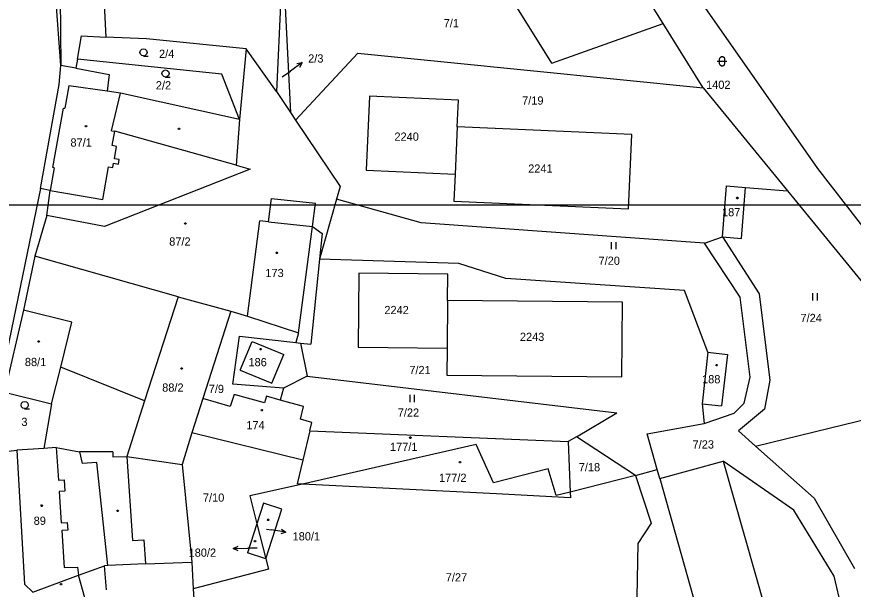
# Model space of a CAD drawing. Extents: x -802857 to -799647, y -1020285 to -1015884.
# Drawn here: x -801490 to -801316.9, y -1017579.5 to -1017461.1 of the extents above; entities that cross this region are included whole.
import ezdxf

# ---------------------------------------------------------------- set-up
doc = ezdxf.new("R2010")
doc.units = 0
for name, color, linetype in [('Default', 7, 'Continuous'), ('KLADY_ZMVM', 7, 'Continuous'), ('KN_HRANICE', 7, 'Continuous'), ('KN_KULTURY', 7, 'Continuous'), ('KN_PARCELY', 7, 'Continuous'), ('KN_SLUCKY', 7, 'Continuous')]:
    doc.layers.add(name, color=color, linetype=linetype)

# ---------------------------------------------------------------- blocks, each defined once
blk = doc.blocks.new('304')
at = {"layer": 'Default'}
blk.add_lwpolyline([(0, 0), (-0.38, 0.1), (-0.65, 0.37), (-0.75, 0.74), (-0.65, 1.11), (-0.38, 1.38), (-0.01, 1.48), (0.36, 1.38), (0.63, 1.11), (0.73, 0.73), (0.63, 0.35), (0.36, 0.08), (-0.02, -0.02), (0.98, -0.02)], dxfattribs=at)
blk = doc.blocks.new('306')
at = {"layer": 'Default'}
for p, q in [((-0.5, 1.5), (-0.5, 0)), ((0.5, 0), (0.5, 1.5))]:
    blk.add_line(p, q, dxfattribs=at)
blk = doc.blocks.new('316')
at = {"layer": 'Default'}
for points in [[(-0.5, 1.5), (-0.4, 1.79), (-0.15, 1.97), (0.16, 1.97), (0.41, 1.79), (0.51, 1.5), (0.51, 0.5), (0.41, 0.21), (0.16, 0.03), (-0.15, 0.03), (-0.4, 0.21), (-0.5, 0.5), (-0.5, 1.5)], [(-1, 1), (0.27, 1), (1, 1)]]:
    blk.add_lwpolyline(points, dxfattribs=at)
blk = doc.blocks.new('NAHRADNI_SYMBOL')
at = {"layer": 'Default'}
blk.add_lwpolyline([(0.09, 0.15), (0.18, 0), (0.09, -0.15), (-0.09, -0.15), (-0.18, 0), (-0.09, 0.15), (0.09, 0.15)], dxfattribs=at)
blk = doc.blocks.new('10292')
at = {"layer": 'Default'}
blk.add_line((0, 3), (0, 0), dxfattribs=at)
blk.add_lwpolyline([(-0.5, 2), (0, 3), (0.5, 2)], dxfattribs=at)
blk = doc.blocks.new('402')
at = {"layer": 'Default'}
blk.add_lwpolyline([(0.09, 0.15), (0.18, 0), (0.09, -0.15), (-0.09, -0.15), (-0.18, 0), (-0.09, 0.15), (0.09, 0.15)], dxfattribs=at)

msp = doc.modelspace()

# ---------------------------------------------------------------- linework, layer by layer
at = {"layer": 'KLADY_ZMVM'}
msp.add_lwpolyline([(-801875, -1017500), (-801250, -1017500), (-801043.11, -1017500)], dxfattribs=at)
at = {"layer": 'KN_HRANICE'}
for p, q in [((-801366.39, -1017432.38), (-801324.28, -1017492.5)), ((-801356.25, -1017462.47), (-801367.72, -1017444.15)), ((-801481.05, -1017452.5), (-801480.85, -1017471.15)), ((-801435.08, -1017451.54), (-801436.26, -1017476.56)), ((-801472.2, -1017452.64), (-801471.55, -1017465.31)), ((-801379.24, -1017470.71), (-801390.25, -1017453.11)), ((-801480.85, -1017471.15), (-801481.99, -1017455.66)), ((-801434.42, -1017459.09), (-801433.35, -1017480.9)), ((-801379.24, -1017470.71), (-801356.25, -1017462.47)), ((-801347.93, -1017475.78), (-801356.25, -1017462.47)), ((-801477.42, -1017469.86), (-801476.6, -1017465.01)), ((-801476.6, -1017465.01), (-801471.55, -1017465.31)), ((-801463.11, -1017465.64), (-801471.55, -1017465.31)), ((-801442.53, -1017467.71), (-801463.11, -1017465.64)), ((-801442.53, -1017467.71), (-801443.87, -1017482.3)), ((-801436.26, -1017476.56), (-801442.53, -1017467.71)), ((-801432.29, -1017482.48), (-801419.41, -1017468.61)), ((-801419.41, -1017468.61), (-801347.93, -1017475.78)), ((-801481.2, -1017475.07), (-801480.85, -1017471.15)), ((-801477.74, -1017471.72), (-801480.85, -1017471.15)), ((-801477.42, -1017469.86), (-801477.74, -1017471.72)), ((-801447.58, -1017472.97), (-801477.42, -1017469.86)), ((-801477.74, -1017471.72), (-801470.85, -1017473.01)), ((-801470.85, -1017473.01), (-801471.25, -1017476.47)), ((-801443.87, -1017482.3), (-801447.58, -1017472.97)), ((-801485.05, -1017496.6), (-801481.2, -1017475.07)), ((-801468.51, -1017476.86), (-801471.25, -1017476.47)), ((-801436.26, -1017476.56), (-801433.35, -1017480.9)), ((-801347.93, -1017475.78), (-801330.52, -1017497.1)), ((-801443.87, -1017482.3), (-801468.51, -1017476.86)), ((-801416.99, -1017477.52), (-801417.67, -1017492.81)), ((-801398.61, -1017478.34), (-801416.99, -1017477.52)), ((-801398.85, -1017483.83), (-801398.61, -1017478.34)), ((-801433.35, -1017480.9), (-801432.29, -1017482.48)), ((-801443.87, -1017482.3), (-801444.57, -1017491.8)), ((-801432.29, -1017482.48), (-801423.09, -1017496.22)), ((-801398.85, -1017483.83), (-801399.29, -1017493.63)), ((-801362.69, -1017485.45), (-801398.85, -1017483.83)), ((-801363.38, -1017500.83), (-801362.69, -1017485.45)), ((-801444.57, -1017491.8), (-801441.67, -1017492.59)), ((-801441.67, -1017492.59), (-801471.82, -1017504.46)), ((-801417.67, -1017492.81), (-801399.29, -1017493.63)), ((-801399.29, -1017493.63), (-801399.54, -1017499.22)), ((-801324.28, -1017492.5), (-801277.94, -1017552.4)), ((-801485.05, -1017496.6), (-801499.12, -1017563.93)), ((-801483.09, -1017497), (-801485.05, -1017496.6)), ((-801483.78, -1017502.18), (-801483.09, -1017497)), ((-801423.09, -1017496.22), (-801423.84, -1017498.84)), ((-801343.98, -1017506.62), (-801343.11, -1017496.06)), ((-801343.11, -1017496.06), (-801339.17, -1017496.38)), ((-801340.04, -1017506.94), (-801339.17, -1017496.38)), ((-801339.17, -1017496.38), (-801330.52, -1017497.1)), ((-801330.52, -1017497.1), (-801295.7, -1017539.76)), ((-801437.92, -1017503.51), (-801437.29, -1017498.66)), ((-801437.29, -1017498.66), (-801428.14, -1017499.64)), ((-801423.84, -1017498.84), (-801427.36, -1017511.23)), ((-801406.29, -1017503.73), (-801423.84, -1017498.84)), ((-801399.54, -1017499.22), (-801363.38, -1017500.83)), ((-801428.78, -1017504.49), (-801428.14, -1017499.64)), ((-801483.78, -1017502.18), (-801486.27, -1017510.58)), ((-801471.82, -1017504.46), (-801483.78, -1017502.18)), ((-801442.26, -1017523.04), (-801439.66, -1017503.32)), ((-801437.92, -1017503.51), (-801439.66, -1017503.32)), ((-801347.66, -1017507.88), (-801406.29, -1017503.73)), ((-801428.78, -1017504.49), (-801426.82, -1017505.92)), ((-801426.82, -1017505.92), (-801427.36, -1017511.23)), ((-801347.66, -1017507.88), (-801343.98, -1017506.62)), ((-801340.3, -1017519.09), (-801347.66, -1017507.88)), ((-801343.98, -1017506.62), (-801336.36, -1017518.38)), ((-801343.98, -1017506.62), (-801340.04, -1017506.94)), ((-801486.27, -1017510.58), (-801488.6, -1017521.78)), ((-801456.61, -1017519.04), (-801486.27, -1017510.58)), ((-801427.36, -1017511.23), (-801429.15, -1017528.81)), ((-801398.49, -1017512.08), (-801427.36, -1017511.23)), ((-801388.8, -1017515.22), (-801398.49, -1017512.08)), ((-801419.19, -1017514.13), (-801419.33, -1017529.43)), ((-801400.8, -1017514.3), (-801419.19, -1017514.13)), ((-801400.84, -1017519.79), (-801400.8, -1017514.3)), ((-801351.85, -1017517.73), (-801388.8, -1017515.22)), ((-801346.97, -1017530.44), (-801351.85, -1017517.73)), ((-801456.61, -1017519.04), (-801445.68, -1017521.95)), ((-801400.84, -1017519.79), (-801400.93, -1017529.6)), ((-801364.65, -1017520.13), (-801400.84, -1017519.79)), ((-801338.24, -1017535.6), (-801340.3, -1017519.09)), ((-801336.36, -1017518.38), (-801334.2, -1017536.23)), ((-801364.79, -1017535.52), (-801364.65, -1017520.13)), ((-801488.6, -1017521.78), (-801492.54, -1017538.69)), ((-801478.58, -1017524.23), (-801488.6, -1017521.78)), ((-801445.68, -1017521.95), (-801451.5, -1017540.03)), ((-801445.68, -1017521.95), (-801442.26, -1017523.04)), ((-801442.26, -1017523.04), (-801431.67, -1017526.43)), ((-801480.88, -1017533.53), (-801478.58, -1017524.23)), ((-801431.67, -1017526.43), (-801432.23, -1017528.46)), ((-801445.24, -1017537.05), (-801443.91, -1017527.13)), ((-801443.91, -1017527.13), (-801432.23, -1017528.46)), ((-801432.23, -1017528.46), (-801431.24, -1017528.57)), ((-801431.24, -1017528.57), (-801429.87, -1017535.4)), ((-801431.24, -1017528.57), (-801429.15, -1017528.81)), ((-801419.33, -1017529.43), (-801400.93, -1017529.6)), ((-801400.93, -1017529.6), (-801400.98, -1017535.2)), ((-801346.97, -1017530.44), (-801348.19, -1017541.12)), ((-801346.97, -1017530.44), (-801342.95, -1017530.9)), ((-801342.95, -1017530.9), (-801344.17, -1017541.58)), ((-801463.52, -1017540.51), (-801480.88, -1017533.53)), ((-801429.87, -1017535.4), (-801434.82, -1017537.87)), ((-801429.87, -1017535.4), (-801365.81, -1017542.99)), ((-801400.98, -1017535.2), (-801364.79, -1017535.52)), ((-801434.82, -1017537.87), (-801445.24, -1017537.05)), ((-801339.5, -1017540.98), (-801338.24, -1017535.6)), ((-801334.2, -1017536.23), (-801335.28, -1017542.24)), ((-801492.54, -1017538.69), (-801482.76, -1017541.15)), ((-801434.82, -1017537.87), (-801435.51, -1017540.35)), ((-801463.52, -1017540.51), (-801467.22, -1017552.01)), ((-801451.5, -1017540.03), (-801453.78, -1017547.11)), ((-801445.8, -1017541.72), (-801451.5, -1017540.03)), ((-801444.98, -1017539.21), (-801445.8, -1017541.72)), ((-801438.72, -1017540.9), (-801444.98, -1017539.21)), ((-801438.33, -1017539.58), (-801438.72, -1017540.9)), ((-801435.51, -1017540.35), (-801438.33, -1017539.58)), ((-801430.65, -1017541.69), (-801435.51, -1017540.35)), ((-801337.12, -1017549.87), (-801295.7, -1017539.76)), ((-801482.76, -1017541.15), (-801484.41, -1017550.34)), ((-801431.26, -1017544.3), (-801430.65, -1017541.69)), ((-801348.19, -1017541.12), (-801344.17, -1017541.58)), ((-801348.19, -1017541.12), (-801347.75, -1017545.2)), ((-801341.56, -1017543.05), (-801339.5, -1017540.98)), ((-801335.28, -1017542.24), (-801340.66, -1017546.73)), ((-801374.14, -1017547.98), (-801365.81, -1017542.99)), ((-801347.75, -1017545.2), (-801341.56, -1017543.05)), ((-801428.9, -1017544.97), (-801431.26, -1017544.3)), ((-801429.31, -1017546.73), (-801428.9, -1017544.97)), ((-801359.52, -1017547.37), (-801347.75, -1017545.2)), ((-801453.78, -1017547.11), (-801455.73, -1017553.67)), ((-801430.77, -1017552.77), (-801453.78, -1017547.11)), ((-801429.31, -1017546.73), (-801430.77, -1017552.77)), ((-801429.31, -1017546.73), (-801375.91, -1017548.92)), ((-801357.47, -1017554.71), (-801359.52, -1017547.37)), ((-801340.66, -1017546.73), (-801337.12, -1017549.87)), ((-801374.14, -1017547.98), (-801375.91, -1017548.92)), ((-801375.91, -1017548.92), (-801375.48, -1017559.38)), ((-801361.94, -1017555.93), (-801374.14, -1017547.98)), ((-801495.13, -1017551.32), (-801489.95, -1017550.72)), ((-801484.41, -1017550.34), (-801489.95, -1017550.72)), ((-801489.95, -1017550.72), (-801488.39, -1017578.43)), ((-801481.83, -1017550.17), (-801484.41, -1017550.34)), ((-801481.83, -1017550.17), (-801476.99, -1017551.09)), ((-801470.08, -1017551.09), (-801476.99, -1017551.09)), ((-801470.08, -1017551.09), (-801470.08, -1017552.09)), ((-801394.95, -1017549.57), (-801430.88, -1017557.72)), ((-801391.34, -1017557.45), (-801394.95, -1017549.57)), ((-801337.12, -1017549.87), (-801324.97, -1017560.63)), ((-801470.08, -1017552.09), (-801467.22, -1017552.01)), ((-801467.22, -1017552.01), (-801455.73, -1017553.67)), ((-801430.77, -1017552.77), (-801431.96, -1017557.66)), ((-801455.73, -1017553.67), (-801453.77, -1017573.85)), ((-801380, -1017554.55), (-801391.34, -1017557.45)), ((-801378.36, -1017560.12), (-801380, -1017554.55)), ((-801356.95, -1017556.58), (-801343.82, -1017553)), ((-801329.23, -1017563.15), (-801343.82, -1017553)), ((-801343.82, -1017553), (-801325.84, -1017616.37)), ((-801361.94, -1017555.93), (-801375.48, -1017559.38)), ((-801361.94, -1017555.93), (-801357.47, -1017554.71)), ((-801361.94, -1017555.93), (-801358.7, -1017565.82)), ((-801356.95, -1017556.58), (-801357.47, -1017554.71)), ((-801430.88, -1017557.72), (-801441.78, -1017560.19)), ((-801430.88, -1017557.72), (-801431.96, -1017557.66)), ((-801390.75, -1017559.77), (-801430.88, -1017557.72)), ((-801379.28, -1017560.36), (-801390.75, -1017559.77)), ((-801375.48, -1017559.38), (-801378.36, -1017560.12)), ((-801375.48, -1017559.38), (-801375.43, -1017560.56)), ((-801441.78, -1017560.19), (-801440.32, -1017565.92)), ((-801375.43, -1017560.56), (-801379.28, -1017560.36)), ((-801324.97, -1017560.63), (-801316.63, -1017575.17)), ((-801438.93, -1017561.69), (-801440.32, -1017565.92)), ((-801435.13, -1017562.93), (-801438.93, -1017561.69)), ((-801438.46, -1017573.2), (-801435.13, -1017562.93)), ((-801320.87, -1017576.78), (-801329.23, -1017563.15)), ((-801440.32, -1017565.92), (-801442.26, -1017571.97)), ((-801440.32, -1017565.92), (-801438.46, -1017573.2)), ((-801358.7, -1017565.82), (-801361.51, -1017570.05)), ((-801361.51, -1017570.05), (-801361.71, -1017581.12)), ((-801438.46, -1017573.2), (-801442.26, -1017571.97)), ((-801438.46, -1017573.2), (-801437.91, -1017575.33)), ((-801477.2, -1017576.6), (-801471.83, -1017574.62)), ((-801471.14, -1017574.59), (-801471.83, -1017574.62)), ((-801471.38, -1017579.57), (-801471.83, -1017574.62)), ((-801463.35, -1017574.26), (-801471.14, -1017574.59)), ((-801463.35, -1017574.26), (-801453.77, -1017573.85)), ((-801453.77, -1017573.85), (-801453.46, -1017579.4)), ((-801437.91, -1017575.33), (-801453.46, -1017579.4)), ((-801486.65, -1017580.08), (-801477.2, -1017576.6)), ((-801314.53, -1017603.45), (-801320.87, -1017576.78)), ((-801486.65, -1017580.08), (-801488.39, -1017578.43)), ((-801453.46, -1017579.4), (-801452.43, -1017597.66))]:
    msp.add_line(p, q, dxfattribs=at)
at = {"layer": 'KN_PARCELY'}
for p, q in [((-801435.04, -1017473.53), (-801433.36, -1017472.32)), ((-801438.29, -1017567.05), (-801437.26, -1017567.21)), ((-801440.24, -1017570.98), (-801442.18, -1017571.01))]:
    msp.add_line(p, q, dxfattribs=at)
at = {"layer": 'KN_SLUCKY'}
for p, q in [((-801479.23, -1017475.34), (-801480.06, -1017480.02)), ((-801471.25, -1017476.47), (-801479.23, -1017475.34)), ((-801470.35, -1017484.66), (-801468.51, -1017476.86)), ((-801482.5, -1017492.28), (-801480.31, -1017479.97)), ((-801480.31, -1017479.97), (-801480.06, -1017480.02)), ((-801470.35, -1017484.66), (-801469.71, -1017484.77)), ((-801470.22, -1017487.73), (-801469.71, -1017484.77)), ((-801444.57, -1017491.8), (-801469.71, -1017484.77)), ((-801469.34, -1017487.89), (-801470.22, -1017487.73)), ((-801469.78, -1017490.45), (-801469.34, -1017487.89)), ((-801468.8, -1017490.62), (-801469.78, -1017490.45)), ((-801482.26, -1017492.32), (-801482.5, -1017492.28)), ((-801472.18, -1017498.91), (-801470.99, -1017492.11)), ((-801470.99, -1017492.11), (-801470.1, -1017492.27)), ((-801470.1, -1017492.27), (-801469.95, -1017491.38)), ((-801469.95, -1017491.38), (-801468.96, -1017491.55)), ((-801468.96, -1017491.55), (-801468.8, -1017490.62)), ((-801482.26, -1017492.32), (-801483.09, -1017497)), ((-801483.09, -1017497), (-801472.18, -1017498.91)), ((-801437.92, -1017503.51), (-801428.78, -1017504.49)), ((-801431.67, -1017526.43), (-801428.78, -1017504.49)), ((-801456.61, -1017519.04), (-801463.52, -1017540.51)), ((-801443.75, -1017534.16), (-801441.3, -1017528.25)), ((-801441.3, -1017528.25), (-801434.74, -1017530.96)), ((-801437.19, -1017536.87), (-801434.74, -1017530.96)), ((-801482.76, -1017541.15), (-801480.88, -1017533.53)), ((-801443.75, -1017534.16), (-801437.19, -1017536.87)), ((-801481.83, -1017550.17), (-801481.37, -1017556.95)), ((-801476.99, -1017551.09), (-801476.44, -1017553.45)), ((-801467.22, -1017552.01), (-801466.02, -1017569.37)), ((-801473.4, -1017553.28), (-801476.44, -1017553.45)), ((-801471.14, -1017574.59), (-801473.4, -1017553.28)), ((-801481.37, -1017556.95), (-801480.17, -1017556.87)), ((-801480.17, -1017556.87), (-801480.01, -1017559.17)), ((-801356.95, -1017556.58), (-801339.49, -1017618.1)), ((-801480.01, -1017559.17), (-801481.21, -1017559.25)), ((-801481.21, -1017559.25), (-801480.77, -1017565.73)), ((-801480.77, -1017565.73), (-801479.52, -1017565.65)), ((-801479.52, -1017565.65), (-801479.41, -1017567.25)), ((-801479.41, -1017567.25), (-801480.66, -1017567.33)), ((-801480.66, -1017567.33), (-801480.14, -1017575)), ((-801466.02, -1017569.37), (-801463.67, -1017569.28)), ((-801463.67, -1017569.28), (-801463.35, -1017574.26)), ((-801480.14, -1017575), (-801477.38, -1017574.92)), ((-801477.38, -1017574.92), (-801477.2, -1017576.6)), ((-801475.91, -1017581.24), (-801477.2, -1017576.6))]:
    msp.add_line(p, q, dxfattribs=at)

# ---------------------------------------------------------------- block references
at = {"layer": 'KN_KULTURY'}
for name, p in [('304', (-801463.74, -1017469.19)), ('316', (-801344.05, -1017471.3)), ('304', (-801459.19, -1017473.55)), ('402', (-801475.64, -1017483.72)), ('402', (-801456.42, -1017484.28)), ('402', (-801340.89, -1017498.58)), ('NAHRADNI_SYMBOL', (-801455.1, -1017503.86)), ('306', (-801366.49, -1017509.17)), ('402', (-801436.17, -1017509.9)), ('306', (-801324.82, -1017519.75)), ('402', (-801485.46, -1017528.24)), ('402', (-801439.54, -1017529.85)), ('402', (-801455.86, -1017533.84)), ('402', (-801345.19, -1017533.12)), ('304', (-801488.34, -1017542.12)), ('306', (-801408.18, -1017540.8)), ('402', (-801439.26, -1017542.45)), ('402', (-801408.53, -1017548.14)), ('402', (-801398.26, -1017553.22)), ('402', (-801484.8, -1017562.2)), ('402', (-801469.1, -1017563.27)), ('402', (-801437.96, -1017565.13)), ('402', (-801440.67, -1017569.55)), ('402', (-801480.82, -1017578.43))]:
    msp.add_blockref(name, p, dxfattribs=at)
at = {"layer": 'KN_PARCELY'}
for p, rotation in [((-801433.36, -1017472.32), -54.155129), ((-801437.26, -1017567.21), -98.960429), ((-801442.18, -1017571.01), 90.928402)]:
    msp.add_blockref('10292', p, dxfattribs=dict(at, rotation=rotation))

# ---------------------------------------------------------------- texts
for s, height, p in [('7/1', 1.7, (-801401.65, -1017463.26)), ('2/4', 1.7, (-801460.54, -1017469.6)), ('2/3', 1.7, (-801429.69, -1017470.56)), ('2/2', 1.7, (-801461.2, -1017476.11)), ('2/3', 0.1, (-801435.19, -1017473.53)), ('1402', 1.7, (-801347.36, -1017476)), ('7/19', 1.7, (-801385.42, -1017479.26)), ('2240', 1.7, (-801411.84, -1017486.73)), ('87/1', 1.7, (-801478.87, -1017487.94)), ('2241', 1.7, (-801384.17, -1017493.33)), ('187', 1.7, (-801344.06, -1017502.34)), ('87/2', 1.7, (-801458.44, -1017508.42)), ('7/20', 1.7, (-801369.61, -1017512.39)), ('173', 1.7, (-801438.54, -1017514.92)), ('2242', 1.7, (-801413.92, -1017522.59)), ('7/24', 1.7, (-801327.83, -1017524.23)), ('2243', 1.7, (-801385.88, -1017528.13)), ('88/1', 1.7, (-801488.3, -1017533.33)), ('186', 1.7, (-801442.04, -1017533.36)), ('7/21', 1.7, (-801408.76, -1017535)), ('188', 1.7, (-801348.19, -1017536.89)), ('88/2', 1.7, (-801459.89, -1017538.62)), ('7/9', 1.7, (-801450.26, -1017538.9)), ('7/22', 1.7, (-801411.15, -1017543.8)), ('3', 1.7, (-801489.02, -1017545.71)), ('174', 1.7, (-801442.48, -1017546.4)), ('177/1', 1.7, (-801412.76, -1017550.89)), ('7/23', 1.7, (-801350.15, -1017550.38)), ('7/18', 1.7, (-801373.7, -1017555.09)), ('177/2', 1.7, (-801402.61, -1017557.27)), ('7/10', 1.7, (-801451.46, -1017561.38)), ('89', 1.7, (-801486.48, -1017566.16)), ('180/1', 0.1, (-801438.53, -1017567.05)), ('180/1', 1.7, (-801432.91, -1017569.38)), ('180/2', 1.7, (-801454.43, -1017572.76)), ('180/2', 0.1, (-801440.49, -1017570.98)), ('7/27', 1.7, (-801401.22, -1017577.87))]:
    msp.add_text(s, height=height, dxfattribs=at).set_placement(p)

doc.saveas('drawing.dxf')
